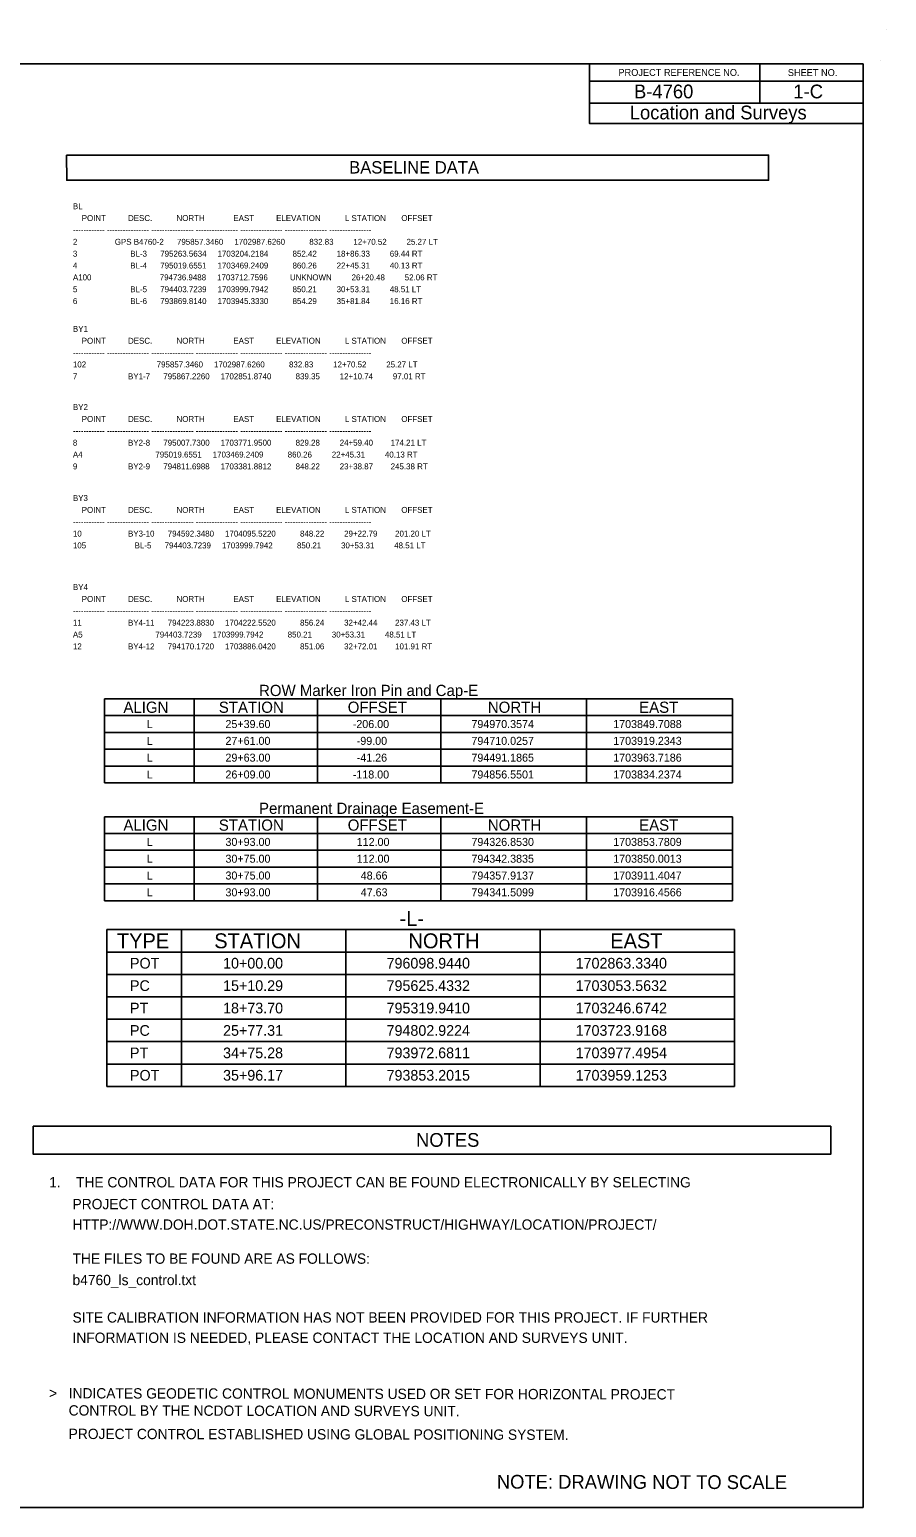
# Model space of a CAD drawing. Extents: x 1701144 to 1707001, y 793349 to 797175.
# Drawn here: x 1704835 to 1707001, y 793436 to 797175 of the extents above; entities that cross this region are included whole.
import ezdxf

# ---------------------------------------------------------------- set-up
doc = ezdxf.new("R2010")
doc.units = 0
for name, color, linetype in [('CTL Sheet Border CELL', 7, 'Continuous'), ('CTL Sheet Notes CELL', 7, 'Continuous'), ('CTL Sheet Table Cell', 7, 'Continuous'), ('CTL Sheet Text', 7, 'Continuous'), ('Old_Level_57', 7, 'Continuous'), ('Sheet Data Field CELL', 7, 'Continuous')]:
    doc.layers.add(name, color=color, linetype=linetype)

msp = doc.modelspace()

# ---------------------------------------------------------------- linework, layer by layer
at = {"layer": 'CTL Sheet Border CELL'}
for points in [[(1706942.2, 797087.9), (1701724.8, 797087.9), (1701724.8, 793435.7), (1706942.2, 793435.7)], [(1704928.5, 796857.3), (1706703.3, 796857.3), (1706703.3, 796793.7), (1704928.6, 796793.7)], [(1704844, 794400), (1706860.7, 794400), (1706860.7, 794329.3), (1704844.1, 794329.3)]]:
    msp.add_lwpolyline(points, close=True, dxfattribs=at)
at = {"layer": 'CTL Sheet Table Cell'}
for p, q in [((1705024.4, 795481.5), (1706612, 795481.5)), ((1705024.4, 795481.5), (1705024.4, 795439)), ((1705251.2, 795481.5), (1705251.2, 795439)), ((1705563, 795481.5), (1705563, 795439)), ((1705874.9, 795481.5), (1705874.9, 795439)), ((1706243.4, 795481.5), (1706243.4, 795439)), ((1706612, 795481.5), (1706612, 795439)), ((1705024.4, 795439), (1706612, 795439)), ((1705024.4, 795439), (1705024.4, 795396.5)), ((1705251.2, 795439), (1705251.2, 795396.5)), ((1705563, 795439), (1705563, 795396.5)), ((1705874.9, 795439), (1705874.9, 795396.5)), ((1706243.4, 795439), (1706243.4, 795396.5)), ((1706612, 795439), (1706612, 795396.5)), ((1705024.4, 795396.5), (1706612, 795396.5)), ((1705024.4, 795396.5), (1705024.4, 795353.9)), ((1705251.2, 795396.5), (1705251.2, 795353.9)), ((1705563, 795396.5), (1705563, 795353.9)), ((1705874.9, 795396.5), (1705874.9, 795353.9)), ((1706243.4, 795396.5), (1706243.4, 795353.9)), ((1706612, 795396.5), (1706612, 795353.9)), ((1705024.4, 795353.9), (1706612, 795353.9)), ((1705024.4, 795353.9), (1705024.4, 795311.4)), ((1705251.2, 795353.9), (1705251.2, 795311.4)), ((1705563, 795353.9), (1705563, 795311.4)), ((1705874.9, 795353.9), (1705874.9, 795311.4)), ((1706243.4, 795353.9), (1706243.4, 795311.4)), ((1706612, 795353.9), (1706612, 795311.4)), ((1705024.4, 795311.4), (1706612, 795311.4)), ((1705024.4, 795311.4), (1705024.4, 795268.9)), ((1705251.2, 795311.4), (1705251.2, 795268.9)), ((1705563, 795311.4), (1705563, 795268.9)), ((1705874.9, 795311.4), (1705874.9, 795268.9)), ((1706243.4, 795311.4), (1706243.4, 795268.9)), ((1706612, 795311.4), (1706612, 795268.9)), ((1705024.4, 795268.9), (1706612, 795268.9)), ((1705024.4, 795183.3), (1706612, 795183.3)), ((1705024.4, 795183.3), (1705024.4, 795140.8)), ((1705251.2, 795183.3), (1705251.2, 795140.8)), ((1705563, 795183.3), (1705563, 795140.8)), ((1705874.9, 795183.3), (1705874.9, 795140.8)), ((1706243.4, 795183.3), (1706243.4, 795140.8)), ((1706612, 795183.3), (1706612, 795140.8)), ((1705024.4, 795140.8), (1706612, 795140.8)), ((1705024.4, 795140.8), (1705024.4, 795098.3)), ((1705251.2, 795140.8), (1705251.2, 795098.3)), ((1705563, 795140.8), (1705563, 795098.3)), ((1705874.9, 795140.8), (1705874.9, 795098.3)), ((1706243.4, 795140.8), (1706243.4, 795098.3)), ((1706612, 795140.8), (1706612, 795098.3)), ((1705024.4, 795098.3), (1706612, 795098.3)), ((1705024.4, 795098.3), (1705024.4, 795055.8)), ((1705251.2, 795098.3), (1705251.2, 795055.8)), ((1705563, 795098.3), (1705563, 795055.8)), ((1705874.9, 795098.3), (1705874.9, 795055.8)), ((1706243.4, 795098.3), (1706243.4, 795055.8)), ((1706612, 795098.3), (1706612, 795055.8)), ((1705024.4, 795055.8), (1706612, 795055.8)), ((1705024.4, 795055.8), (1705024.4, 795013.2)), ((1705251.2, 795055.8), (1705251.2, 795013.2)), ((1705563, 795055.8), (1705563, 795013.2)), ((1705874.9, 795055.8), (1705874.9, 795013.2)), ((1706243.4, 795055.8), (1706243.4, 795013.2)), ((1706612, 795055.8), (1706612, 795013.2)), ((1705024.4, 795013.2), (1706612, 795013.2)), ((1705024.4, 795013.2), (1705024.4, 794970.7)), ((1705251.2, 795013.2), (1705251.2, 794970.7)), ((1705563, 795013.2), (1705563, 794970.7)), ((1705874.9, 795013.2), (1705874.9, 794970.7)), ((1706243.4, 795013.2), (1706243.4, 794970.7)), ((1706612, 795013.2), (1706612, 794970.7)), ((1705024.4, 794970.7), (1706612, 794970.7)), ((1705029.9, 794897.7), (1706617.5, 794897.7)), ((1705029.9, 794897.7), (1705029.9, 794841)), ((1705218.9, 794897.7), (1705218.9, 794841)), ((1705634.7, 794897.7), (1705634.7, 794841)), ((1706126.1, 794897.7), (1706126.1, 794841)), ((1706617.5, 794897.7), (1706617.5, 794841)), ((1705029.9, 794841), (1706617.5, 794841)), ((1705029.9, 794841), (1705029.9, 794784.3)), ((1705218.9, 794841), (1705218.9, 794784.3)), ((1705634.7, 794841), (1705634.7, 794784.3)), ((1706126.1, 794841), (1706126.1, 794784.3)), ((1706617.5, 794841), (1706617.5, 794784.3)), ((1705029.9, 794784.3), (1706617.5, 794784.3)), ((1705029.9, 794784.3), (1705029.9, 794727.6)), ((1705218.9, 794784.3), (1705218.9, 794727.6)), ((1705634.7, 794784.3), (1705634.7, 794727.6)), ((1706126.1, 794784.3), (1706126.1, 794727.6)), ((1706617.5, 794784.3), (1706617.5, 794727.6)), ((1705029.9, 794727.6), (1706617.5, 794727.6)), ((1705029.9, 794727.6), (1705029.9, 794670.9)), ((1705218.9, 794727.6), (1705218.9, 794670.9)), ((1705634.7, 794727.6), (1705634.7, 794670.9)), ((1706126.1, 794727.6), (1706126.1, 794670.9)), ((1706617.5, 794727.6), (1706617.5, 794670.9)), ((1705029.9, 794670.9), (1706617.5, 794670.9)), ((1705029.9, 794670.9), (1705029.9, 794614.2)), ((1705218.9, 794670.9), (1705218.9, 794614.2)), ((1705634.7, 794670.9), (1705634.7, 794614.2)), ((1706126.1, 794670.9), (1706126.1, 794614.2)), ((1706617.5, 794670.9), (1706617.5, 794614.2)), ((1705029.9, 794614.2), (1706617.5, 794614.2)), ((1705029.9, 794614.2), (1705029.9, 794557.5)), ((1705218.9, 794614.2), (1705218.9, 794557.5)), ((1705634.7, 794614.2), (1705634.7, 794557.5)), ((1706126.1, 794614.2), (1706126.1, 794557.5)), ((1706617.5, 794614.2), (1706617.5, 794557.5)), ((1705029.9, 794557.5), (1706617.5, 794557.5)), ((1705029.9, 794557.5), (1705029.9, 794500.8)), ((1705218.9, 794557.5), (1705218.9, 794500.8)), ((1705634.7, 794557.5), (1705634.7, 794500.8)), ((1706126.1, 794557.5), (1706126.1, 794500.8)), ((1706617.5, 794557.5), (1706617.5, 794500.8)), ((1705029.9, 794500.8), (1706617.5, 794500.8))]:
    msp.add_line(p, q, dxfattribs=at)
at = {"layer": 'Sheet Data Field CELL'}
for p, q in [((1707001.4, 797174.8), (1707001.4, 797174.8)), ((1706250.3, 797087.7), (1706250.3, 796988.7)), ((1706681.4, 797087.7), (1706681.4, 796988.7)), ((1706985.7, 797096.8), (1706985.7, 797096.8)), ((1706985.7, 797096.8), (1706985.7, 797096.8)), ((1706250.3, 797044.2), (1706942.2, 797044.2))]:
    msp.add_line(p, q, dxfattribs=at)
msp.add_lwpolyline([(1706250.3, 796988.7), (1706942.2, 796988.7), (1706942.2, 796937.5), (1706250.3, 796937.5)], close=True, dxfattribs=at)

# ---------------------------------------------------------------- texts
at = {"layer": 'CTL Sheet Notes CELL'}
for s, p in [('ROW Marker Iron Pin and Cap-E', (1705415, 795488.6)), ('ALIGN', (1705072.1, 795446.1)), ('STATION', (1705313.3, 795446.1)), ('OFFSET', (1705639.2, 795446.1)), ('NORTH', (1705993.5, 795446.1)), ('EAST', (1706376.1, 795446.1)), ('Permanent Drainage Easement-E', (1705415, 795190.4)), ('ALIGN', (1705072.1, 795147.9)), ('STATION', (1705313.3, 795147.9)), ('OFFSET', (1705639.2, 795147.9)), ('NORTH', (1705993.5, 795147.9)), ('EAST', (1706376.1, 795147.9))]:
    msp.add_text(s, height=28.35, dxfattribs=at).set_placement(p)
at = {"layer": 'CTL Sheet Table Cell'}
for s, height, p in [('-L-', 37.8, (1705770.4, 794907.1)), ('TYPE', 37.8, (1705055.7, 794850.4)), ('STATION', 37.8, (1705301.8, 794850.4)), ('NORTH', 37.8, (1705792.9, 794850.4)), ('EAST', 37.8, (1706303.1, 794850.4)), ('POT', 27, (1705088.7, 794799.1)), ('10+00.00', 27, (1705324.1, 794799.1)), ('796098.9440', 27, (1705737.5, 794799.1)), ('1702863.3340', 27, (1706215.6, 794799.1)), ('PC ', 27, (1705088.7, 794742.4)), ('15+10.29', 27, (1705324.1, 794742.4)), ('795625.4332', 27, (1705737.5, 794742.4)), ('1703053.5632', 27, (1706215.6, 794742.4)), ('PT ', 27, (1705088.7, 794685.7)), ('18+73.70', 27, (1705324.1, 794685.7)), ('795319.9410', 27, (1705737.5, 794685.7)), ('1703246.6742', 27, (1706215.6, 794685.7)), ('PC ', 27, (1705088.7, 794629)), ('25+77.31', 27, (1705324.1, 794629)), ('794802.9224', 27, (1705737.5, 794629)), ('1703723.9168', 27, (1706215.6, 794629)), ('PT ', 27, (1705088.7, 794572.3)), ('34+75.28', 27, (1705324.1, 794572.3)), ('793972.6811', 27, (1705737.5, 794572.3)), ('1703977.4954', 27, (1706215.6, 794572.3)), ('POT', 27, (1705088.7, 794515.6)), ('35+96.17', 27, (1705324.1, 794515.6)), ('793853.2015', 27, (1705737.5, 794515.6)), ('1703959.1253', 27, (1706215.6, 794515.6))]:
    msp.add_text(s, height=height, dxfattribs=at).set_placement(p)
at = {"layer": 'CTL Sheet Text'}
for s, height, p in [('BASELINE DATA', 31.304, (1705643, 796810.6)), ('BL', 15, (1704944.4, 796720.3)), ('    POINT          DESC.           NORTH             EAST          ELEVATION           L STATION       OFFSET', 15, (1704944.4, 796690.3)), ('------------ ---------------- ---------------- ---------------- ---------------- ---------------- ----------------', 15, (1704944.4, 796660.3)), ('3                        BL-3      795263.5634     1703204.2184           852.42         18+86.33         69.44 RT', 15, (1704944.4, 796600.3)), ('2                 GPS B4760-2      795857.3460     1702987.6260           832.83         12+70.52         25.27 LT', 15, (1704944.4, 796630.3)), ('4                        BL-4      795019.6551     1703469.2409           860.26         22+45.31         40.13 RT', 15, (1704944.4, 796570.3)), ('A100                               794736.9488     1703712.7596          UNKNOWN         26+20.48         52.06 RT', 15, (1704944.4, 796540.3)), ('5                        BL-5      794403.7239     1703999.7942           850.21         30+53.31         48.51 LT', 15, (1704944.4, 796510.3)), ('6                        BL-6      793869.8140     1703945.3330           854.29         35+81.84         16.16 RT', 15, (1704944.4, 796480.3)), ('BY1', 15, (1704944.4, 796410)), ('    POINT          DESC.           NORTH             EAST          ELEVATION           L STATION       OFFSET', 15, (1704944.4, 796380)), ('------------ ---------------- ---------------- ---------------- ---------------- ---------------- ----------------', 15, (1704944.4, 796350)), ('102                                795857.3460     1702987.6260           832.83         12+70.52         25.27 LT', 15, (1704944.4, 796320)), ('7                       BY1-7      795867.2260     1702851.8740           839.35         12+10.74         97.01 RT', 15, (1704944.4, 796290)), ('BY2', 15, (1704944.4, 796212.1)), ('    POINT          DESC.           NORTH             EAST          ELEVATION           L STATION       OFFSET', 15, (1704944.4, 796182.1)), ('------------ ---------------- ---------------- ---------------- ---------------- ---------------- ----------------', 15, (1704944.4, 796152.1)), ('8                       BY2-8      795007.7300     1703771.9500           829.28         24+59.40        174.21 LT', 15, (1704944.4, 796122.1)), ('A4                                 795019.6551     1703469.2409           860.26         22+45.31         40.13 RT', 15, (1704944.4, 796092.1)), ('9                       BY2-9      794811.6988     1703381.8812           848.22         23+38.87        245.38 RT', 15, (1704944.4, 796062.1)), ('BY3', 15, (1704944.4, 795982.1)), ('    POINT          DESC.           NORTH             EAST          ELEVATION           L STATION       OFFSET', 15, (1704944.4, 795952.1)), ('------------ ---------------- ---------------- ---------------- ---------------- ---------------- ----------------', 15, (1704944.4, 795922.1)), ('10                     BY3-10      794592.3480     1704095.5220           848.22         29+22.79        201.20 LT', 15, (1704944.4, 795892.1)), ('105                      BL-5      794403.7239     1703999.7942           850.21         30+53.31         48.51 LT', 15, (1704944.4, 795862.1)), ('BY4', 15, (1704944.4, 795756.7)), ('    POINT          DESC.           NORTH             EAST          ELEVATION           L STATION       OFFSET', 15, (1704944.4, 795726.7)), ('------------ ---------------- ---------------- ---------------- ---------------- ---------------- ----------------', 15, (1704944.4, 795696.7)), ('11                     BY4-11      794223.8830     1704222.5520           856.24         32+42.44        237.43 LT', 15, (1704944.4, 795666.7)), ('A5                                 794403.7239     1703999.7942           850.21         30+53.31         48.51 LT', 15, (1704944.4, 795636.7)), ('12                     BY4-12      794170.1720     1703886.0420           851.06         32+72.01        101.91 RT', 15, (1704944.4, 795606.7)), ('L', 20.2, (1705131.1, 795407.6)), ('25+39.60', 20.25, (1705330.1, 795407.6)), ('-206.00', 20.25, (1705652, 795407.6)), ('794970.3574', 20.25, (1705952, 795407.6)), ('1703849.7088', 20.25, (1706310.5, 795407.6)), ('L', 20.2, (1705131.1, 795365.1)), ('27+61.00', 20.25, (1705330.1, 795365.1)), ('-99.00', 20.25, (1705662, 795365.1)), ('794710.0257', 20.25, (1705952, 795365.1)), ('1703919.2343', 20.25, (1706310.5, 795365.1)), ('L', 20.2, (1705131.1, 795322.6)), ('29+63.00', 20.25, (1705330.1, 795322.6)), ('-41.26', 20.25, (1705662, 795322.6)), ('794491.1865', 20.25, (1705952, 795322.6)), ('1703963.7186', 20.25, (1706310.5, 795322.6)), ('L', 20.2, (1705131.1, 795280)), ('26+09.00', 20.25, (1705330.1, 795280)), ('-118.00', 20.25, (1705652, 795280)), ('794856.5501', 20.25, (1705952, 795280)), ('1703834.2374', 20.25, (1706310.5, 795280)), ('L', 20.2, (1705131.1, 795109.4)), ('30+93.00', 20.25, (1705330.1, 795109.4)), ('112.00', 20.25, (1705662, 795109.4)), ('794326.8530', 20.25, (1705952, 795109.4)), ('1703853.7809', 20.25, (1706310.5, 795109.4)), ('L', 20.2, (1705131.1, 795066.9)), ('30+75.00', 20.25, (1705330.1, 795066.9)), ('112.00', 20.25, (1705662, 795066.9)), ('794342.3835', 20.25, (1705952, 795066.9)), ('1703850.0013', 20.25, (1706310.5, 795066.9)), ('30+75.00', 20.25, (1705330.1, 795024.4)), ('48.66', 20.25, (1705672.1, 795024.4)), ('794357.9137', 20.25, (1705952, 795024.4)), ('1703911.4047', 20.25, (1706310.5, 795024.4)), ('L', 20.2, (1705131.1, 795024.4)), ('L', 20.2, (1705131.1, 794981.9)), ('30+93.00', 20.25, (1705330.1, 794981.9)), ('47.63', 20.25, (1705672.1, 794981.9)), ('794341.5099', 20.25, (1705952, 794981.9)), ('1703916.4566', 20.25, (1706310.5, 794981.9))]:
    msp.add_text(s, height=height, dxfattribs=at).set_placement(p)
msp.add_text('NOTES', height=34.78, rotation=360, dxfattribs=at).set_placement((1705811.9, 794348.1))
at = {"layer": 'Old_Level_57'}
msp.add_text('>', height=26.1, rotation=0.0142, dxfattribs=at).set_placement((1704884, 793712))
at = {"layer": 'Sheet Data Field CELL'}
for s, height, p in [('PROJECT REFERENCE NO.', 17.392, (1706323.7, 797057.6)), ('SHEET NO.', 17.39, (1706752, 797057.3)), ('B-4760', 34.78, (1706363.1, 797000.8)), ('1-C', 34.78, (1706766.1, 797000.8)), ('Location and Surveys', 34.783, (1706352.4, 796947.6))]:
    msp.add_text(s, height=height, dxfattribs=at).set_placement(p)
for s, height, rotation, p in [('1.    THE CONTROL DATA FOR THIS PROJECT CAN BE FOUND ELECTRONICALLY BY SELECTING', 26.087, 360, (1704884.3, 794245.4)), ('PROJECT CONTROL DATA AT:', 26.087, 360, (1704943.4, 794190.2)), ('HTTP://WWW.DOH.DOT.STATE.NC.US/PRECONSTRUCT/HIGHWAY/LOCATION/PROJECT/', 26.087, 360, (1704943.4, 794138.4)), ('THE FILES TO BE FOUND ARE AS FOLLOWS:', 26.087, 360, (1704943.4, 794052.2)), ('b4760_ls_control.txt', 26.087, 360, (1704943.4, 793998.1)), ('SITE CALIBRATION INFORMATION HAS NOT BEEN PROVIDED FOR THIS PROJECT. IF FURTHER', 26.087, 360, (1704943.4, 793903.4)), ('INFORMATION IS NEEDED, PLEASE CONTACT THE LOCATION AND SURVEYS UNIT.', 26.087, 360, (1704943.4, 793852)), ('INDICATES GEODETIC CONTROL MONUMENTS USED OR SET FOR HORIZONTAL PROJECT', 26.087, 359.8948, (1704933.8, 793711.6)), ('CONTROL BY THE NCDOT LOCATION AND SURVEYS UNIT.', 26.087, 359.8948, (1704933.6, 793668.2)), ('PROJECT CONTROL ESTABLISHED USING GLOBAL POSITIONING SYSTEM.', 26.087, 359.8948, (1704933.6, 793608.9)), ('NOTE: DRAWING NOT TO SCALE', 34.783, 359.8948, (1706016.2, 793483.4))]:
    msp.add_text(s, height=height, rotation=rotation, dxfattribs=at).set_placement(p)

doc.saveas('drawing.dxf')
